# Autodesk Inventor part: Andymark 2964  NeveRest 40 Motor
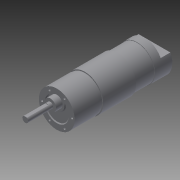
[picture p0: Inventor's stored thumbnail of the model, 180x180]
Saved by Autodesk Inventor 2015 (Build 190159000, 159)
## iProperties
Created: 2014-08
Part Number: Andymark 2964  NeveRest 40 Motor
Material: Generic
Document SubType Name: Modeling
Designer: Austin
Density: 1 g/cm^3
Appearance: Default
Author: Austin
Title: am-2964NeveRest.STEP
Description: STEP AP203
Creation Date: 2014-07-17
Sending System: SolidWorks 2014
Preprocessor: SwSTEP 2.0
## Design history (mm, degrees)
node "am-2964NeveRest (2)1"
node "Boss-Extrude10"
node "Base1"
